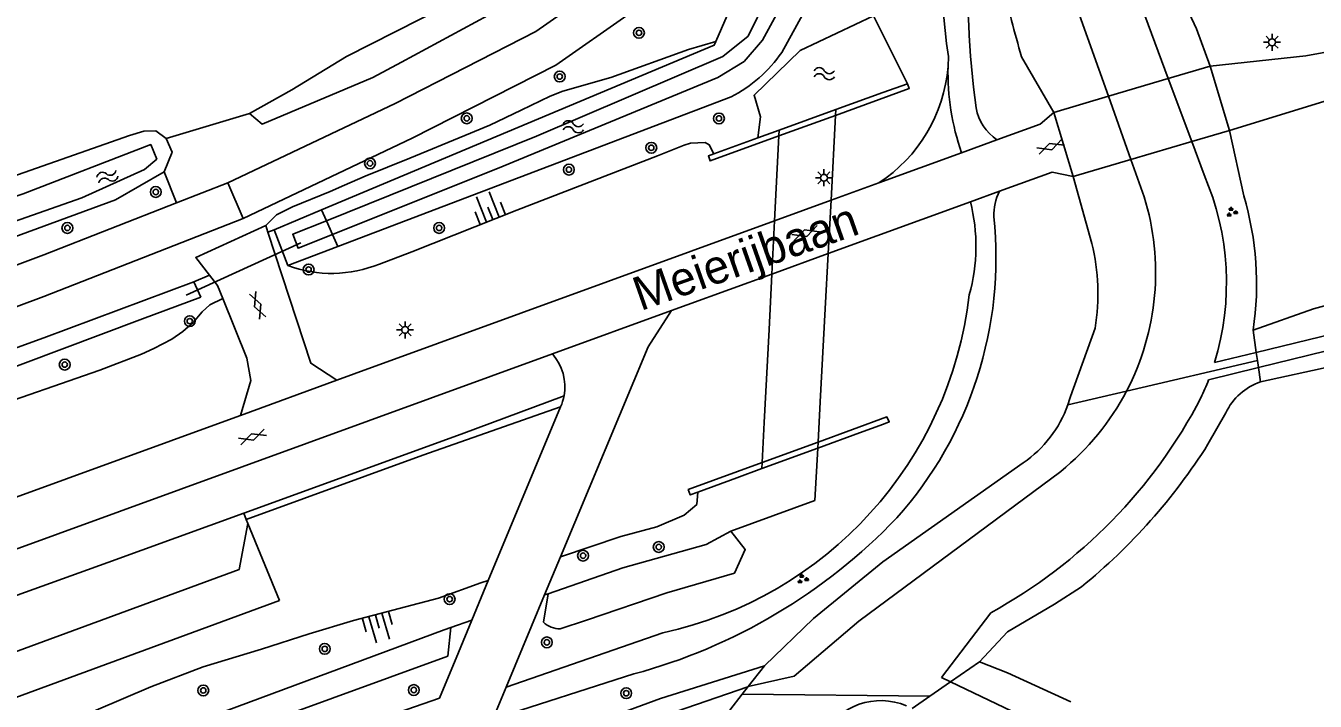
# Model space of a CAD drawing. Extents: x 135999 to 138000, y 396000 to 398501.
# Drawn here: x 136498.7 to 136593.9, y 396147 to 396196.9 of the extents above; entities that cross this region are included whole.
import ezdxf

# ---------------------------------------------------------------- set-up
doc = ezdxf.new("R2010")
doc.units = 0
for name, color, linetype in [('gg-afsc-muur', 7, 'Continuous'), ('gg-anno-openbare ruimte label', 7, 'Continuous'), ('gg-knt-BGT kruinlijn', 7, 'Continuous'), ('gg-knt-bronhoudergrens', 7, 'Continuous'), ('gg-knt-onverhard', 7, 'Continuous'), ('gg-knt-verharding', 7, 'Continuous'), ('gg-kntw-bovenkant insteek waterloop', 7, 'Continuous'), ('gg-kntw-waterlijn', 7, 'Continuous'), ('gg-kwrk-duiker nz buis', 7, 'Continuous'), ('gg-kwrk-duiker nz vlak', 7, 'Continuous'), ('gg-kwrk-kunstwerk niveau 01', 7, 'Continuous'), ('gt-grn-groengrens', 7, 'Continuous'), ('gt-grn-vlakafsluiter', 7, 'Continuous'), ('gt-grn-weggrens', 7, 'Continuous'), ('gt-symb-boom', 7, 'Continuous'), ('gt-symb-gesloten verharding', 7, 'Continuous'), ('gt-symb-groenvak', 7, 'Continuous'), ('gt-symb-lichtmast', 7, 'Continuous'), ('gt-symb-talud symbool', 7, 'Continuous'), ('gt-symb-watersymbool', 7, 'Continuous'), ('gx-grn-maaiveld', 7, 'Continuous')]:
    doc.layers.add(name, color=color, linetype=linetype)

# ---------------------------------------------------------------- blocks, each defined once
blk = doc.blocks.new('gt0-WA')
at = {"layer": 'gt-symb-watersymbool'}
for centre, start, end in [((-0.323, 0.022), 28.07249, 151.92751), ((0.427, 0.422), 208.07248, 331.92751), ((-0.323, -0.428), 28.07249, 151.92751), ((0.427, -0.028), 208.07248, 331.92751)]:
    blk.add_arc(centre, 0.425, start, end, dxfattribs=at)
blk = doc.blocks.new('gt0-GESVH1')
at = {"layer": 'gt-symb-gesloten verharding'}
for p, q in [((-0.992, -0.261), (0.008, 0.239)), ((0.008, -0.261), (-0.992, 0.239)), ((0.008, 0.239), (1.008, -0.261)), ((1.008, 0.239), (0.008, -0.261))]:
    blk.add_line(p, q, dxfattribs=at)
blk = doc.blocks.new('gt0-BOOM')
at = {"layer": 'gt-symb-boom'}
for radius in [0.4, 0.2]:
    blk.add_circle((0, 0), radius, dxfattribs=at)
blk = doc.blocks.new('gt0-TALUD_1')
at = {"layer": 'gt-symb-talud symbool'}
for p, q in [((-1, -1), (-1, 0)), ((-0.5, -2), (-0.5, 0)), ((0, -1), (0, 0)), ((0.5, -2), (0.5, 0)), ((1, -1), (1, 0))]:
    blk.add_line(p, q, dxfattribs=at)
blk = doc.blocks.new('gt0-LMAST')
at = {"layer": 'gt-symb-lichtmast'}
for p, q in [((-0.182, 0.173), (-0.447, 0.438)), ((-0.005, 0.246), (-0.005, 0.621)), ((0.172, 0.173), (0.437, 0.438)), ((-0.255, -0.004), (-0.63, -0.004)), ((-0.182, -0.181), (-0.447, -0.446)), ((-0.005, -0.254), (-0.005, -0.629)), ((0.437, -0.446), (0.172, -0.181)), ((0.245, -0.004), (0.62, -0.004))]:
    blk.add_line(p, q, dxfattribs=at)
blk.add_circle((-0.005, -0.004), 0.25, dxfattribs=at)
blk = doc.blocks.new('gt0-GRVAK')
at = {"layer": 'gt-symb-groenvak'}
for p, q in [((-0.11, 0.189), (-0.228, 0.24)), ((-0.182, 0.153), (0.088, 0.153)), ((-0.091, 0.211), (-0.156, 0.322)), ((-0.047, 0.214), (-0.047, 0.393)), ((-0.004, 0.211), (0.061, 0.322)), ((0.015, 0.189), (0.133, 0.24)), ((0.262, -0.052), (0.197, 0.059)), ((0.305, -0.049), (0.305, 0.13)), ((0.349, -0.052), (0.414, 0.059)), ((-0.245, -0.228), (-0.363, -0.177)), ((-0.318, -0.264), (-0.047, -0.264)), ((-0.226, -0.206), (-0.291, -0.095)), ((-0.183, -0.203), (-0.183, -0.024)), ((-0.139, -0.206), (-0.074, -0.095)), ((-0.12, -0.228), (-0.002, -0.177)), ((0.243, -0.074), (0.125, -0.023)), ((0.17, -0.11), (0.441, -0.11)), ((0.368, -0.074), (0.486, -0.023))]:
    blk.add_line(p, q, dxfattribs=at)

msp = doc.modelspace()

# ---------------------------------------------------------------- linework, layer by layer
at = {"layer": 'gg-afsc-muur'}
for p, q in [((136561.962, 396191.981), (136563.769, 396192.637)), ((136558.487, 396190.719), (136561.962, 396191.981)), ((136554.304, 396189.2), (136558.487, 396190.719)), ((136554.282, 396188.777), (136558.464, 396190.296)), ((136552.733, 396188.63), (136554.304, 396189.2)), ((136549.475, 396187.446), (136552.733, 396188.63)), ((136560.242, 396166.852), (136557.152, 396165.72)), ((136562.012, 396167.501), (136560.242, 396166.852)), ((136553.044, 396164.651), (136557.176, 396166.166)), ((136557.152, 396165.72), (136553.021, 396164.206)), ((136553.021, 396164.206), (136551.172, 396163.528)), ((136551.172, 396163.528), (136548.305, 396162.478))]:
    msp.add_line(p, q, dxfattribs=at)
for points in [[(136558.464, 396190.296), (136563.903, 396192.271), (136563.769, 396192.637)], [(136549.475, 396187.446), (136549.078, 396187.302), (136549.204, 396186.932), (136554.282, 396188.777)], [(136557.176, 396166.166), (136562.254, 396168.027), (136562.429, 396167.654), (136562.012, 396167.501)], [(136548.305, 396162.478), (136547.733, 396162.268), (136547.592, 396162.653), (136553.044, 396164.651)]]:
    msp.add_lwpolyline(points, dxfattribs=at)
at = {"layer": 'gg-knt-BGT kruinlijn'}
for p, q in [((136548.23, 396161.566), (136548.305, 396162.478)), ((136547.294, 396160.769), (136548.23, 396161.566)), ((136545.275, 396159.905), (136547.294, 396160.769)), ((136538.158, 396157.691), (136542.602, 396159.196)), ((136542.602, 396159.196), (136545.275, 396159.905))]:
    msp.add_line(p, q, dxfattribs=at)
for points in [[(136524.784, 396179.316), (136527.188, 396180.218), (136534.921, 396183.3), (136545.323, 396187.309), (136547.294, 396188.098), (136547.76, 396188.233), (136548.824, 396188.28), (136549.138, 396188.121), (136549.475, 396187.446)], [(136513.223, 396176.773), (136512.267, 396176.312), (136511.703, 396175.791), (136511.018, 396175.006), (136510.273, 396174.332), (136509.447, 396173.767), (136508.12, 396173.069), (136507.203, 396172.665), (136504.131, 396171.475), (136495.476, 396168.477), (136491.032, 396166.683), (136487.362, 396165.282), (136482.586, 396163.649), (136480.714, 396162.943), (136477.672, 396161.706), (136466.728, 396157.838), (136464.011, 396156.813), (136459.131, 396154.879), (136451.951, 396152.379), (136447.715, 396151.004)], [(136435.187, 396121.807), (136439.031, 396123.037), (136442.687, 396124.488), (136449.83, 396127.198), (136453.734, 396128.526), (136457.896, 396129.885), (136462.015, 396131.35), (136466.284, 396132.751), (136470.577, 396134.458), (136474.697, 396135.923), (136478.927, 396137.481), (136489.875, 396140.911), (136493.044, 396142.041), (136496.599, 396143.5), (136500, 396144.715), (136507.897, 396148.082), (136511.761, 396149.567), (136516.073, 396150.862), (136519.603, 396152.015), (136522.862, 396152.984), (136529.152, 396154.633), (136532.27, 396155.768), (136532.824, 396155.944)]]:
    msp.add_lwpolyline(points, dxfattribs=at)
msp.add_arc((136521.26, 396187.939), 9.315, 249.70519, 292.22851, dxfattribs=at)
at = {"layer": 'gg-knt-bronhoudergrens'}
msp.add_line((136509.04, 396188.581), (136515.182, 396190.431), dxfattribs=at)
msp.add_lwpolyline([(136515.182, 396190.431), (136518.308, 396192.187), (136522.363, 396194.643), (136542.253, 396204.755), (136545.428, 396207.533), (136552.691, 396219.562)], dxfattribs=at)
at = {"layer": 'gg-knt-onverhard'}
msp.add_line((136509.794, 396183.835), (136513.584, 396185.322), dxfattribs=at)
for points in [[(136513.584, 396185.322), (136525.94, 396191.184), (136536.32, 396196.483), (136546.67, 396203.725)], [(136514.726, 396182.683), (136527.209, 396188.606), (136537.804, 396194.014), (136548.786, 396201.699)], [(136422.009, 396151.715), (136434.974, 396156.127), (136452.042, 396162.225), (136466.648, 396167.77), (136483.244, 396173.724), (136500, 396179.992), (136509.794, 396183.835)], [(136422.717, 396148.92), (136435.92, 396153.413), (136453.036, 396159.528), (136467.643, 396165.074), (136484.233, 396171.026), (136500, 396176.923), (136514.726, 396182.683)]]:
    msp.add_lwpolyline(points, dxfattribs=at)
msp.add_arc((136555.492, 396194.792), 11.311, 303.01194, 355.44596, dxfattribs=at)
at = {"layer": 'gg-knt-verharding'}
for p, q in [((136566.768, 396193.894), (136566.803, 396194.651)), ((136567.772, 396187.535), (136570.381, 396188.485)), ((136561.655, 396185.307), (136567.772, 396187.535)), ((136558.129, 396184.023), (136561.655, 396185.307)), ((136553.96, 396182.505), (136558.129, 396184.023)), ((136557.919, 396180.088), (136568.427, 396183.912)), ((136568.427, 396183.912), (136570.564, 396184.69)), ((136516.553, 396181.671), (136516.39, 396182.168)), ((136553.759, 396178.573), (136557.919, 396180.088)), ((136123.238, 396021.871), (136537.553, 396172.674)), ((136532.824, 396155.944), (136538.164, 396168.78)), ((136514.941, 396160.46), (136515.071, 396160.143)), ((136515.071, 396160.143), (136517.404, 396154.458)), ((136536.981, 396154.873), (136538.158, 396157.691)), ((136531.602, 396153.006), (136532.824, 396155.944)), ((136536.018, 396152.567), (136536.981, 396154.873)), ((136530.612, 396150.627), (136531.602, 396153.006)), ((136534.143, 396148.076), (136536.018, 396152.567)), ((136534.143, 396148.076), (136545.706, 396152.084)), ((136529.21, 396147.257), (136530.612, 396150.627)), ((136543.569, 396149.041), (136533.156, 396145.714)), ((136533.156, 396145.714), (136534.143, 396148.076))]:
    msp.add_line(p, q, dxfattribs=at)
for points in [[(136586.128, 396193.937), (136593.184, 396194.698), (136604.32, 396196.746)], [(136587.557, 396189.182), (136594.511, 396191.312), (136594.896, 396191.355)], [(136570.381, 396188.485), (136573.573, 396189.648), (136574.568, 396190.52)], [(136570.564, 396184.69), (136574.451, 396186.105), (136576.008, 396185.782)], [(136516.39, 396182.168), (136511.225, 396179.789), (136512.237, 396178.498)], [(136521.648, 396170.736), (136522.907, 396171.195), (136553.96, 396182.505)], [(136521.648, 396170.736), (136519.726, 396171.992), (136516.553, 396181.671)], [(136512.237, 396178.498), (136512.834, 396177.738), (136513.223, 396176.773)], [(136546.354, 396175.878), (136547.502, 396176.295), (136553.759, 396178.573)], [(136513.223, 396176.773), (136515.003, 396172.36), (136515.282, 396170.727), (136514.518, 396168.14)], [(136538.158, 396157.691), (136544.632, 396173.193), (136546.354, 396175.878)], [(136427.256, 396136.357), (136513.375, 396167.723), (136514.518, 396168.14)], [(136428.692, 396125.481), (136431.063, 396126.076), (136514.438, 396156.767), (136515.071, 396160.143)], [(136122.438, 396010.85), (136448.93, 396129.29), (136517.404, 396154.458)], [(136442.682, 396116.883), (136472.778, 396127.423), (136500.27, 396137.208), (136529.21, 396147.257)]]:
    msp.add_lwpolyline(points, dxfattribs=at)
for centre, radius, start, end in [((136634.913, 396199.886), 66.685, 166.73946, 187.78756), ((136613.385, 396201.896), 47.142, 170.0782, 188.84064), ((136584.617, 396193.453), 17.854, 178.58564, 199.35869), ((136572.388, 396191.473), 3.599, 189.96488, 236.1084), ((136555.383, 396180.652), 13.445, 344.43336, 14.03172), ((136573.973, 396182.954), 3.825, 153.01902, 182.01422), ((136541.412, 396179.792), 28.897, 318.27728, 6.01497), ((136539.593, 396180.364), 28.933, 282.19685, 353.41158), ((136534.828, 396170.252), 3.646, 349.40142, 41.64107), ((136534.829, 396170.252), 3.645, 336.19269, 349.4009), ((136532.638, 396189.575), 41.982, 285.0917, 316.28032)]:
    msp.add_arc(centre, radius, start, end, dxfattribs=at)
at = {"layer": 'gg-kntw-bovenkant insteek waterloop'}
for p, q in [((136550.873, 396198.638), (136549.626, 396195.745)), ((136563.769, 396192.637), (136561.264, 396197.644)), ((136572.201, 396194.626), (136574.568, 396190.52)), ((136587.557, 396189.182), (136588.6, 396184.356)), ((136576.008, 396185.782), (136577.385, 396180.827)), ((136517.021, 396181.849), (136518.029, 396179.202)), ((136511.584, 396176.86), (136511.09, 396178.002)), ((136577.62, 396174.586), (136575.815, 396169.53)), ((136595.045, 396171.747), (136589.842, 396170.608)), ((136587.28, 396168.335), (136585.961, 396166.003)), ((136536.897, 396152.862), (136537.249, 396154.966)), ((136529.846, 396150.349), (136530.046, 396152.466)), ((136553.204, 396149.64), (136545.543, 396147.235))]:
    msp.add_line(p, q, dxfattribs=at)
for points in [[(136564.71, 396214.592), (136557.137, 396199.757), (136554.492, 396194.943)], [(136586.128, 396193.937), (136585.117, 396196.687), (136582.719, 396201.802)], [(136561.264, 396197.644), (136555.856, 396195.094), (136552.444, 396191.777), (136552.92, 396190.191), (136552.733, 396188.63)], [(136509.04, 396188.581), (136508.265, 396189.157), (136507.39, 396189.124), (136506.338, 396188.799), (136494.881, 396184.794), (136479.396, 396179.164), (136475.28, 396177.135), (136474.982, 396177.026)], [(136508.894, 396186.13), (136509.472, 396187.572), (136509.04, 396188.581)], [(136468.94, 396174.822), (136468.475, 396173.526), (136468.937, 396172.258), (136469.869, 396171.721), (136471.422, 396171.904), (136490.592, 396178.674), (136505.291, 396184.059), (136508.894, 396186.13)], [(136589.294, 396174.439), (136593.745, 396176.003), (136611.28, 396180.81)], [(136511.09, 396178.002), (136500, 396173.875), (136483.248, 396167.773), (136469.989, 396163.041), (136430.36, 396149.398), (136423.313, 396147.05)], [(136424.491, 396145.617), (136438.772, 396150.673), (136458.07, 396157.125), (136489.786, 396168.684), (136507.299, 396175.28), (136511.584, 396176.86)], [(136572.323, 396164.633), (136561.942, 396157.313), (136556.835, 396153.131), (136553.204, 396149.64)], [(136537.249, 396154.966), (136542.762, 396156.88), (136548.902, 396158.593), (136550.724, 396159.576)], [(136550.724, 396159.576), (136551.793, 396158.239), (136550.995, 396156.48)], [(136550.995, 396156.48), (136546.015, 396155.039), (136540.084, 396153.026), (136538.139, 396152.38)], [(136576.631, 396155.484), (136574.629, 396154.197), (136571.171, 396152.163), (136569.1, 396149.945)], [(136370.462, 396092.387), (136386.173, 396098.255), (136415.76, 396110.14), (136429.322, 396115.464), (136442.758, 396120.489), (136459.652, 396127.032), (136477.254, 396133.468), (136493.989, 396139.305), (136512.535, 396145.971), (136529.565, 396152.299), (136530.046, 396152.466)], [(136138.46, 396000), (136141.913, 396001.073), (136162.747, 396009.253), (136190.803, 396019.776), (136218.845, 396030.09), (136247.225, 396040.686), (136275.033, 396051.955), (136297.31, 396061.218), (136314.079, 396068.107), (136321.558, 396071.282), (136333.532, 396075.963), (136346.555, 396081.585), (136376.91, 396093.459), (136391.259, 396098.976), (136405.938, 396104.773), (136420.841, 396110.809), (136453.103, 396122.787), (136472.551, 396129.843), (136491.902, 396136.959), (136512.799, 396144.154), (136529.846, 396150.349)], [(136569.1, 396149.945), (136571.155, 396149.133), (136575.832, 396146.985)], [(136510.476, 396135.003), (136536.914, 396144.044), (136545.543, 396147.235)]]:
    msp.add_lwpolyline(points, dxfattribs=at)
for centre, radius, start, end in [((136546.01, 396200.825), 10.322, 297.35774, 325.26315), ((136566.821, 396177.849), 22.73, 351.37172, 16.63444), ((136562.426, 396177.139), 15.407, 350.46241, 13.85041), ((136591.272, 396166.416), 4.429, 108.83514, 154.32357), ((136548.932, 396189.449), 43.827, 309.19748, 327.65862), ((136538.085, 396154.081), 1.702, 225.75014, 271.82901)]:
    msp.add_arc(centre, radius, start, end, dxfattribs=at)
at = {"layer": 'gg-kntw-waterlijn'}
for p, q in [((136580.806, 396199.019), (136583.032, 396193.022)), ((136576.361, 396198.033), (136578.607, 396191.714)), ((136584.763, 396188.359), (136583.032, 396193.022)), ((136580.269, 396187.036), (136578.607, 396191.714)), ((136584.763, 396188.359), (136585.677, 396185.897)), ((136580.269, 396187.036), (136581.244, 396184.29)), ((136589.53, 396172.788), (136586.446, 396172.038)), ((136586.007, 396170.761), (136589.691, 396171.665)), ((136569.917, 396153.556), (136566.284, 396148.785)), ((136552.012, 396148.11), (136555.403, 396148.884)), ((136566.284, 396148.785), (136566.954, 396148.462))]:
    msp.add_line(p, q, dxfattribs=at)
for points in [[(136589.691, 396171.665), (136608.284, 396176.227), (136638.361, 396183.269), (136638.186, 396184.015), (136632.07, 396183.175), (136618.4, 396179.913), (136608.296, 396177.352), (136598.107, 396174.874), (136589.53, 396172.788)], [(136575.085, 396164.005), (136560.184, 396152.93), (136555.403, 396148.884)], [(136441.8, 396109.93), (136451.818, 396113.091), (136468.495, 396118.906), (136494.321, 396128.173), (136522.016, 396137.746), (136540.603, 396144.17), (136551.976, 396148.101), (136552.012, 396148.11)], [(136566.954, 396148.462), (136572.033, 396146.013), (136573.341, 396145.936), (136594.029, 396137.214), (136619.774, 396125.244)]]:
    msp.add_lwpolyline(points, dxfattribs=at)
for centre, radius, start, end in [((136567.247, 396177.924), 20.08, 342.95638, 23.3955), ((136567.411, 396177.861), 19.905, 334.94927, 339.10211), ((136551.449, 396187.147), 38.333, 298.80086, 332.47622), ((136561.798, 396142.179), 4.893, 67.25564, 150.64408)]:
    msp.add_arc(centre, radius, start, end, dxfattribs=at)
at = {"layer": 'gg-kwrk-duiker nz buis'}
msp.add_line((136518.975, 396180.873), (136510.505, 396177.013), dxfattribs=at)
at = {"layer": 'gg-kwrk-duiker nz vlak'}
for p, q in [((136558.487, 396190.719), (136558.464, 396190.296)), ((136558.464, 396190.296), (136558.129, 396184.023)), ((136554.282, 396188.777), (136553.96, 396182.505)), ((136554.304, 396189.2), (136554.282, 396188.777)), ((136558.129, 396184.023), (136557.919, 396180.088)), ((136553.96, 396182.505), (136553.759, 396178.573)), ((136557.919, 396180.088), (136557.701, 396176.001)), ((136553.759, 396178.573), (136553.549, 396174.492)), ((136557.701, 396176.001), (136557.334, 396169.135)), ((136553.549, 396174.492), (136553.196, 396167.614)), ((136557.334, 396169.135), (136557.176, 396166.166)), ((136553.196, 396167.614), (136553.044, 396164.651)), ((136557.176, 396166.166), (136557.152, 396165.72)), ((136553.044, 396164.651), (136553.021, 396164.206))]:
    msp.add_line(p, q, dxfattribs=at)
at = {"layer": 'gg-kwrk-kunstwerk niveau 01'}
for p, q in [((136586.128, 396193.937), (136583.032, 396193.022)), ((136587.557, 396189.182), (136586.128, 396193.937)), ((136583.032, 396193.022), (136578.607, 396191.714)), ((136578.607, 396191.714), (136574.568, 396190.52)), ((136574.568, 396190.52), (136576.008, 396185.782)), ((136584.763, 396188.359), (136587.557, 396189.182)), ((136580.269, 396187.036), (136584.763, 396188.359)), ((136576.008, 396185.782), (136580.269, 396187.036))]:
    msp.add_line(p, q, dxfattribs=at)
at = {"layer": 'gt-grn-groengrens'}
for p, q in [((136509.794, 396183.835), (136508.894, 396186.13)), ((136516.553, 396181.671), (136517.021, 396181.849)), ((136511.09, 396178.002), (136512.237, 396178.498)), ((136557.152, 396165.72), (136556.945, 396161.856)), ((136550.724, 396159.576), (136556.945, 396161.856)), ((136514.941, 396160.46), (136514.777, 396160.91)), ((136536.981, 396154.873), (136537.249, 396154.966)), ((136530.046, 396152.466), (136531.602, 396153.006))]:
    msp.add_line(p, q, dxfattribs=at)
for points in [[(136545.5, 396205.397), (136538.241, 396200.645), (136526.401, 396194.236)], [(136516.39, 396182.168), (136517.174, 396182.939), (136518.376, 396183.531), (136521.147, 396184.681), (136522.216, 396185.153), (136523.719, 396185.818), (136527.036, 396187.132), (136531.087, 396188.815), (136532.932, 396189.582), (136535.251, 396190.692), (136537.384, 396191.714), (136538.314, 396192.074), (136541.858, 396193.105), (136547.603, 396195.16), (136549.626, 396195.745)], [(136526.401, 396194.236), (136524.294, 396193.096), (136516.114, 396189.649), (136515.182, 396190.431)], [(136514.777, 396160.91), (136530.822, 396166.739), (136538.412, 396169.581)], [(136538.164, 396168.78), (136527.983, 396165.199), (136514.941, 396160.46)], [(136426.12, 396128.781), (136438.89, 396133.355), (136460.256, 396141.19), (136478.607, 396147.861), (136504.738, 396157.262), (136514.777, 396160.91)]]:
    msp.add_lwpolyline(points, dxfattribs=at)
at = {"layer": 'gt-grn-vlakafsluiter'}
for p, q in [((136589.53, 396172.788), (136589.294, 396174.439)), ((136589.842, 396170.608), (136589.691, 396171.665)), ((136552.012, 396148.11), (136553.204, 396149.64)), ((136566.954, 396148.462), (136569.1, 396149.945))]:
    msp.add_line(p, q, dxfattribs=at)
at = {"layer": 'gt-grn-weggrens'}
for p, q in [((136514.726, 396182.683), (136513.584, 396185.322)), ((136546.354, 396175.878), (136537.553, 396172.674)), ((136514.518, 396168.14), (136521.648, 396170.736))]:
    msp.add_line(p, q, dxfattribs=at)
at = {"layer": 'gx-grn-maaiveld'}
for p, q in [((136550.753, 396191.657), (136521.712, 396180.604)), ((136517.021, 396181.849), (136520.515, 396183.314)), ((136520.515, 396183.314), (136520.866, 396182.519)), ((136520.866, 396182.519), (136521.316, 396181.501)), ((136521.712, 396180.604), (136521.316, 396181.501)), ((136518.029, 396179.202), (136521.712, 396180.604)), ((136589.53, 396172.788), (136589.615, 396172.194)), ((136579.947, 396169.937), (136589.615, 396172.194)), ((136589.615, 396172.194), (136589.691, 396171.665)), ((136575.624, 396168.928), (136579.947, 396169.937)), ((136551.57, 396147.542), (136552.012, 396148.11)), ((136565.42, 396147.401), (136566.954, 396148.462)), ((136551.57, 396147.542), (136550.647, 396146.357)), ((136565.42, 396147.401), (136551.57, 396147.542)), ((136564.119, 396146.502), (136565.42, 396147.401))]:
    msp.add_line(p, q, dxfattribs=at)
for points in [[(136520.866, 396182.519), (136536.39, 396188.757), (136550.147, 396194.639), (136552, 396196.142), (136554.739, 396201.746), (136561.095, 396215.882), (136565.126, 396221.164), (136566.791, 396222.564), (136567.365, 396221.881), (136566.225, 396219.798), (136563.227, 396215.865), (136561.861, 396213.499), (136555.431, 396200.202), (136553.065, 396195.86), (136551.714, 396194.28), (136549.772, 396193.099), (136533.908, 396186.537), (136521.316, 396181.501)], [(136549.626, 396195.745), (136549.51, 396195.475), (136520.515, 396183.314)], [(136473.8, 396176.731), (136472.749, 396175.188), (136486.403, 396180.451), (136498.482, 396184.496), (136507.903, 396188.139), (136508.337, 396187.069), (136507.441, 396186.289), (136502.817, 396184.207), (136488.215, 396179.085), (136469.98, 396172.636), (136469.402, 396173.995), (136471.049, 396174.632), (136471.5, 396175.324), (136472.23, 396176.297)], [(136520.866, 396182.519), (136518.381, 396181.52), (136518.773, 396180.484), (136521.316, 396181.501)]]:
    msp.add_lwpolyline(points, dxfattribs=at)
for centre, radius, start, end in [((136633.043, 396212.824), 63.505, 191.63593, 196.65159), ((136563.225, 396178.683), 18.871, 332.38913, 17.28392), ((136563.224, 396178.685), 18.873, 308.93723, 332.38514), ((136567.325, 396171.89), 8.811, 304.55357, 340.35697), ((136567.594, 396171.807), 8.53, 340.27542, 344.51864)]:
    msp.add_arc(centre, radius, start, end, dxfattribs=at)

# ---------------------------------------------------------------- block references
at = {"layer": 'gt-symb-boom'}
for p in [(136543.948, 396196.392), (136538.097, 396193.166), (136531.23, 396190.077), (136549.851, 396190.068), (136544.854, 396187.904), (136524.087, 396186.752), (136538.773, 396186.29), (136508.268, 396184.638), (136501.743, 396181.981), (136529.192, 396181.981), (136519.553, 396178.908), (136510.783, 396175.097), (136501.546, 396171.89), (136545.406, 396158.418), (136539.819, 396157.778), (136529.968, 396154.567), (136537.148, 396151.374), (136520.746, 396150.896), (136511.776, 396147.82), (136527.322, 396147.854), (136543.003, 396147.62)]:
    msp.add_blockref('gt0-BOOM', p, dxfattribs=at)
at = {"layer": 'gt-symb-gesloten verharding'}
for p, rotation in [((136574.356, 396187.982), -160.42327443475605), ((136556.24, 396181.602), 19.26841496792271), ((136515.782, 396176.247), 111.97171039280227), ((136515.422, 396166.538), -160.42327443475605)]:
    msp.add_blockref('gt0-GESVH1', p, dxfattribs=dict(at, rotation=rotation))
at = {"layer": 'gt-symb-groenvak'}
for p in [(136587.709, 396183.15), (136556.017, 396156.048)]:
    msp.add_blockref('gt0-GRVAK', p, dxfattribs=at)
at = {"layer": 'gt-symb-lichtmast'}
for p in [(136590.697, 396195.697), (136557.613, 396185.693), (136526.683, 396174.454)]:
    msp.add_blockref('gt0-LMAST', p, dxfattribs=at)
at = {"layer": 'gt-symb-talud symbool'}
for p, xscale, yscale, rotation in [((136533.154, 396182.597), 0.9999929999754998, 0.9999929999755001, -158.5922600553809), ((136524.49, 396153.387), 0.9994418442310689, 0.9994418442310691, 16.150135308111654)]:
    msp.add_blockref('gt0-TALUD_1', p, dxfattribs=dict(at, xscale=xscale, yscale=yscale, rotation=rotation))
at = {"layer": 'gt-symb-watersymbool'}
for p in [(136557.577, 396193.375), (136539.048, 396189.457)]:
    msp.add_blockref('gt0-WA', p, dxfattribs=at)
at = {"layer": 'gt-symb-watersymbool', "rotation": 19.44956876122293}
msp.add_blockref('gt0-WA', (136504.644, 396185.752), dxfattribs=at)

# ---------------------------------------------------------------- texts
at = {"layer": 'gg-anno-openbare ruimte label'}
msp.add_text('Meierijbaan', height=2.5, rotation=19.4, dxfattribs=at).set_placement((136544.065, 396175.833))

doc.saveas('drawing.dxf')
